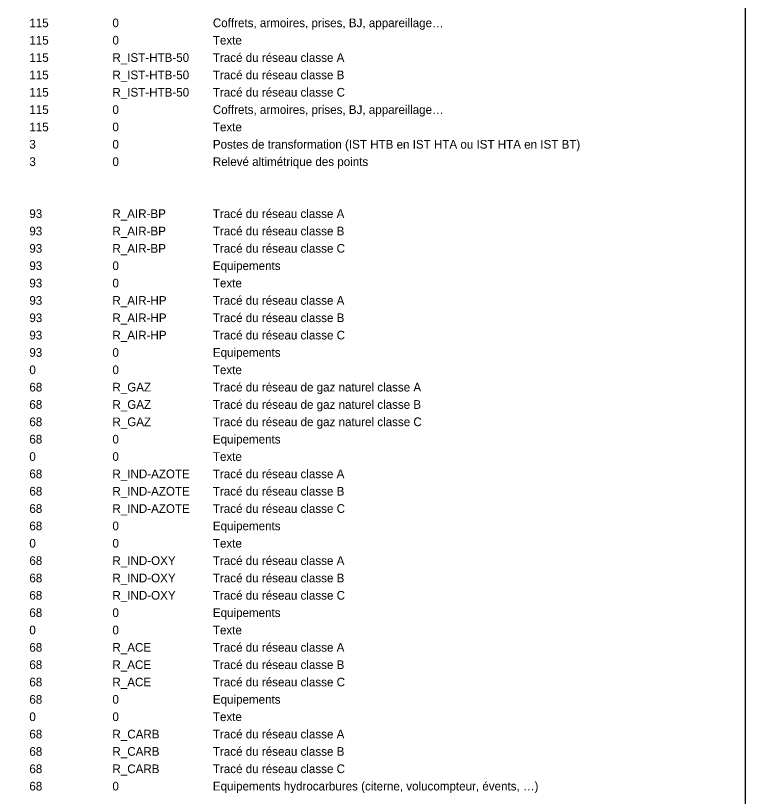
# Model space of a CAD drawing. Extents: x -60 to 214, y -380 to -21.
# Drawn here: x 72.77 to 114.84, y -155.95 to -110.94 of the extents above; entities that cross this region are included whole.
import ezdxf

# ---------------------------------------------------------------- set-up
doc = ezdxf.new("R2010")
doc.units = 0
for name, color, linetype in [('Default', 7, 'Continuous'), ('R_ELEC_IST_ALT_POINT', 7, 'Continuous'), ('R_ELEC_IST_HTA_60HZ_EQUIP', 7, 'Continuous'), ('R_ELEC_IST_HTA_60HZ_TEXTE', 7, 'Continuous'), ('R_ELEC_IST_HTB_50HZ_EQUIP', 7, 'Continuous'), ('R_ELEC_IST_HTB_50HZ_LIAISON_CL_A', 7, 'Continuous'), ('R_ELEC_IST_HTB_50HZ_LIAISON_CL_B', 7, 'Continuous'), ('R_ELEC_IST_HTB_50HZ_LIAISON_CL_C', 7, 'Continuous'), ('R_ELEC_IST_HTB_50HZ_TEXTE', 7, 'Continuous'), ('R_ELEC_IST_POSTE', 7, 'Continuous'), ('R_IND_ACETYLENE_CANALISATION_CL_A', 7, 'Continuous'), ('R_IND_ACETYLENE_CANALISATION_CL_B', 7, 'Continuous'), ('R_IND_ACETYLENE_CANALISATION_CL_C', 7, 'Continuous'), ('R_IND_ACETYLENE_EQUIP', 7, 'Continuous'), ('R_IND_ACETYLENE_TEXTE', 7, 'Continuous'), ('R_IND_AIR_BP_CANALISATION_CL_A', 7, 'Continuous'), ('R_IND_AIR_BP_CANALISATION_CL_B', 7, 'Continuous'), ('R_IND_AIR_BP_CANALISATION_CL_C', 7, 'Continuous'), ('R_IND_AIR_BP_EQUIP', 7, 'Continuous'), ('R_IND_AIR_BP_TEXTE', 7, 'Continuous'), ('R_IND_AIR_HP_CANALISATION_CL_A', 7, 'Continuous'), ('R_IND_AIR_HP_CANALISATION_CL_B', 7, 'Continuous'), ('R_IND_AIR_HP_CANALISATION_CL_C', 7, 'Continuous'), ('R_IND_AIR_HP_EQUIP', 7, 'Continuous'), ('R_IND_AIR_HP_TEXTE', 7, 'Continuous'), ('R_IND_AZOTE_CANALISATION_CL_A', 7, 'Continuous'), ('R_IND_AZOTE_CANALISATION_CL_B', 7, 'Continuous'), ('R_IND_AZOTE_CANALISATION_CL_C', 7, 'Continuous'), ('R_IND_AZOTE_EQUIP', 7, 'Continuous'), ('R_IND_AZOTE_TEXTE', 7, 'Continuous'), ('R_IND_GAZ_NAT_CANALISATION_CL_A', 7, 'Continuous'), ('R_IND_GAZ_NAT_CANALISATION_CL_B', 7, 'Continuous'), ('R_IND_GAZ_NAT_CANALISATION_CL_C', 7, 'Continuous'), ('R_IND_GAZ_NAT_EQUIP', 7, 'Continuous'), ('R_IND_GAZ_NAT_TEXTE', 7, 'Continuous'), ('R_IND_HYDROCARBURE_CANALISATION_CL_A', 7, 'Continuous'), ('R_IND_HYDROCARBURE_CANALISATION_CL_B', 7, 'Continuous'), ('R_IND_HYDROCARBURE_CANALISATION_CL_C', 7, 'Continuous'), ('R_IND_HYDROCARBURE_EQUIP', 7, 'Continuous'), ('R_IND_OXYGENE_CANALISATION_CL_A', 7, 'Continuous'), ('R_IND_OXYGENE_CANALISATION_CL_B', 7, 'Continuous'), ('R_IND_OXYGENE_CANALISATION_CL_C', 7, 'Continuous'), ('R_IND_OXYGENE_EQUIP', 7, 'Continuous'), ('R_IND_OXYGENE_TEXTE', 7, 'Continuous')]:
    doc.layers.add(name, color=color, linetype=linetype)

msp = doc.modelspace()

# ---------------------------------------------------------------- linework, layer by layer
at = {"layer": 'Default'}
msp.add_lwpolyline([(114.838, -25.727), (33.073, -25.727), (33.073, -380.216), (114.838, -380.216)], close=True, dxfattribs=at)

# ---------------------------------------------------------------- texts
at = {"layer": 'R_ELEC_IST_ALT_POINT'}
for s, p in [('3 ', (73.561, -119.61)), ('0 ', (78.351, -119.61)), ('Relevé altimétrique des points ', (84.14, -119.61))]:
    msp.add_text(s, height=0.5, dxfattribs=at).set_placement(p)
at = {"layer": 'R_ELEC_IST_HTA_60HZ_EQUIP'}
for s, p in [('115 ', (73.561, -111.61)), ('0 ', (78.351, -111.61)), ('Coffrets, armoires, prises, BJ, appareillage…', (84.14, -111.61))]:
    msp.add_text(s, height=0.5, dxfattribs=at).set_placement(p)
at = {"layer": 'R_ELEC_IST_HTA_60HZ_TEXTE'}
for s, p in [('115', (73.561, -112.61)), ('0 ', (78.351, -112.61)), ('Texte ', (84.14, -112.61))]:
    msp.add_text(s, height=0.5, dxfattribs=at).set_placement(p)
at = {"layer": 'R_ELEC_IST_HTB_50HZ_EQUIP'}
for s, p in [('115 ', (73.561, -116.61)), ('0 ', (78.351, -116.61)), ('Coffrets, armoires, prises, BJ, appareillage…', (84.14, -116.61))]:
    msp.add_text(s, height=0.5, dxfattribs=at).set_placement(p)
at = {"layer": 'R_ELEC_IST_HTB_50HZ_LIAISON_CL_A'}
for s, p in [('115 ', (73.561, -113.61)), ('R_IST-HTB-50 ', (78.351, -113.61)), ('Tracé du réseau classe A ', (84.14, -113.61))]:
    msp.add_text(s, height=0.5, dxfattribs=at).set_placement(p)
at = {"layer": 'R_ELEC_IST_HTB_50HZ_LIAISON_CL_B'}
for s, p in [('115 ', (73.561, -114.61)), ('R_IST-HTB-50 ', (78.351, -114.61)), ('Tracé du réseau classe B ', (84.14, -114.61))]:
    msp.add_text(s, height=0.5, dxfattribs=at).set_placement(p)
at = {"layer": 'R_ELEC_IST_HTB_50HZ_LIAISON_CL_C'}
for s, p in [('115 ', (73.561, -115.61)), ('R_IST-HTB-50 ', (78.351, -115.61)), ('Tracé du réseau classe C ', (84.14, -115.61))]:
    msp.add_text(s, height=0.5, dxfattribs=at).set_placement(p)
at = {"layer": 'R_ELEC_IST_HTB_50HZ_TEXTE'}
for s, p in [('115 ', (73.561, -117.61)), ('0 ', (78.351, -117.61)), ('Texte ', (84.14, -117.61))]:
    msp.add_text(s, height=0.5, dxfattribs=at).set_placement(p)
at = {"layer": 'R_ELEC_IST_POSTE'}
for s, p in [('3 ', (73.561, -118.61)), ('0 ', (78.351, -118.61)), ('Postes de transformation (IST HTB en IST HTA ou IST HTA en IST BT) ', (84.14, -118.61))]:
    msp.add_text(s, height=0.5, dxfattribs=at).set_placement(p)
at = {"layer": 'R_IND_ACETYLENE_CANALISATION_CL_A'}
for s, p in [('68 ', (73.561, -147.61)), ('R_ACE ', (78.351, -147.61)), ('Tracé du réseau classe A ', (84.14, -147.61))]:
    msp.add_text(s, height=0.5, dxfattribs=at).set_placement(p)
at = {"layer": 'R_IND_ACETYLENE_CANALISATION_CL_B'}
for s, p in [('Tracé du réseau classe B ', (84.14, -148.61)), ('68 ', (73.561, -148.61)), ('R_ACE ', (78.351, -148.61))]:
    msp.add_text(s, height=0.5, dxfattribs=at).set_placement(p)
at = {"layer": 'R_IND_ACETYLENE_CANALISATION_CL_C'}
for s, p in [('68 ', (73.561, -149.61)), ('R_ACE ', (78.351, -149.61)), ('Tracé du réseau classe C ', (84.14, -149.61))]:
    msp.add_text(s, height=0.5, dxfattribs=at).set_placement(p)
at = {"layer": 'R_IND_ACETYLENE_EQUIP'}
for s, p in [('68 ', (73.561, -150.61)), ('0 ', (78.351, -150.61)), ('Equipements ', (84.14, -150.61))]:
    msp.add_text(s, height=0.5, dxfattribs=at).set_placement(p)
at = {"layer": 'R_IND_ACETYLENE_TEXTE'}
for s, p in [('0', (73.561, -151.61)), ('0 ', (78.351, -151.61)), ('Texte ', (84.14, -151.61))]:
    msp.add_text(s, height=0.5, dxfattribs=at).set_placement(p)
at = {"layer": 'R_IND_AIR_BP_CANALISATION_CL_A'}
for s, p in [('93 ', (73.559, -122.61)), ('R_AIR-BP ', (78.348, -122.61)), ('Tracé du réseau classe A ', (84.138, -122.61))]:
    msp.add_text(s, height=0.5, dxfattribs=at).set_placement(p)
at = {"layer": 'R_IND_AIR_BP_CANALISATION_CL_B'}
for s, p in [('93 ', (73.561, -123.61)), ('R_AIR-BP ', (78.351, -123.61)), ('Tracé du réseau classe B ', (84.14, -123.61))]:
    msp.add_text(s, height=0.5, dxfattribs=at).set_placement(p)
at = {"layer": 'R_IND_AIR_BP_CANALISATION_CL_C'}
for s, p in [('93 ', (73.561, -124.61)), ('R_AIR-BP ', (78.351, -124.61)), ('Tracé du réseau classe C ', (84.14, -124.61))]:
    msp.add_text(s, height=0.5, dxfattribs=at).set_placement(p)
at = {"layer": 'R_IND_AIR_BP_EQUIP'}
for s, p in [('93 ', (73.561, -125.61)), ('0 ', (78.351, -125.61)), ('Equipements  ', (84.14, -125.61))]:
    msp.add_text(s, height=0.5, dxfattribs=at).set_placement(p)
at = {"layer": 'R_IND_AIR_BP_TEXTE'}
for s, p in [('93 ', (73.561, -126.61)), ('0 ', (78.351, -126.61)), ('Texte ', (84.14, -126.61))]:
    msp.add_text(s, height=0.5, dxfattribs=at).set_placement(p)
at = {"layer": 'R_IND_AIR_HP_CANALISATION_CL_A'}
for s, p in [('93 ', (73.561, -127.61)), ('R_AIR-HP ', (78.351, -127.61)), ('Tracé du réseau classe A ', (84.14, -127.61))]:
    msp.add_text(s, height=0.5, dxfattribs=at).set_placement(p)
at = {"layer": 'R_IND_AIR_HP_CANALISATION_CL_B'}
for s, p in [('93 ', (73.561, -128.61)), ('R_AIR-HP ', (78.351, -128.61)), ('Tracé du réseau classe B ', (84.14, -128.61))]:
    msp.add_text(s, height=0.5, dxfattribs=at).set_placement(p)
at = {"layer": 'R_IND_AIR_HP_CANALISATION_CL_C'}
for s, p in [('93 ', (73.561, -129.61)), ('R_AIR-HP ', (78.351, -129.61)), ('Tracé du réseau classe C ', (84.14, -129.61))]:
    msp.add_text(s, height=0.5, dxfattribs=at).set_placement(p)
at = {"layer": 'R_IND_AIR_HP_EQUIP'}
for s, p in [('93 ', (73.561, -130.61)), ('0 ', (78.351, -130.61)), ('Equipements ', (84.14, -130.61))]:
    msp.add_text(s, height=0.5, dxfattribs=at).set_placement(p)
at = {"layer": 'R_IND_AIR_HP_TEXTE'}
for s, p in [('0', (73.561, -131.61)), ('0 ', (78.351, -131.61)), ('Texte ', (84.14, -131.61))]:
    msp.add_text(s, height=0.5, dxfattribs=at).set_placement(p)
at = {"layer": 'R_IND_AZOTE_CANALISATION_CL_A'}
for s, p in [('68 ', (73.561, -137.61)), ('R_IND-AZOTE ', (78.351, -137.61)), ('Tracé du réseau classe A ', (84.14, -137.61))]:
    msp.add_text(s, height=0.5, dxfattribs=at).set_placement(p)
at = {"layer": 'R_IND_AZOTE_CANALISATION_CL_B'}
for s, p in [('68 ', (73.561, -138.61)), ('R_IND-AZOTE ', (78.351, -138.61)), ('Tracé du réseau classe B ', (84.14, -138.61))]:
    msp.add_text(s, height=0.5, dxfattribs=at).set_placement(p)
at = {"layer": 'R_IND_AZOTE_CANALISATION_CL_C'}
for s, p in [('Tracé du réseau classe C ', (84.14, -139.61)), ('68 ', (73.561, -139.61)), ('R_IND-AZOTE ', (78.351, -139.61))]:
    msp.add_text(s, height=0.5, dxfattribs=at).set_placement(p)
at = {"layer": 'R_IND_AZOTE_EQUIP'}
for s, p in [('68 ', (73.561, -140.61)), ('0 ', (78.351, -140.61)), ('Equipements ', (84.14, -140.61))]:
    msp.add_text(s, height=0.5, dxfattribs=at).set_placement(p)
at = {"layer": 'R_IND_AZOTE_TEXTE'}
for s, p in [('0', (73.561, -141.61)), ('0 ', (78.351, -141.61)), ('Texte ', (84.14, -141.61))]:
    msp.add_text(s, height=0.5, dxfattribs=at).set_placement(p)
at = {"layer": 'R_IND_GAZ_NAT_CANALISATION_CL_A'}
for s, p in [('68 ', (73.561, -132.61)), ('R_GAZ ', (78.351, -132.61)), ('Tracé du réseau de gaz naturel classe A ', (84.14, -132.61))]:
    msp.add_text(s, height=0.5, dxfattribs=at).set_placement(p)
at = {"layer": 'R_IND_GAZ_NAT_CANALISATION_CL_B'}
for s, p in [('68 ', (73.561, -133.61)), ('R_GAZ ', (78.351, -133.61)), ('Tracé du réseau de gaz naturel classe B ', (84.14, -133.61))]:
    msp.add_text(s, height=0.5, dxfattribs=at).set_placement(p)
at = {"layer": 'R_IND_GAZ_NAT_CANALISATION_CL_C'}
for s, p in [('68 ', (73.561, -134.61)), ('R_GAZ ', (78.351, -134.61)), ('Tracé du réseau de gaz naturel classe C ', (84.14, -134.61))]:
    msp.add_text(s, height=0.5, dxfattribs=at).set_placement(p)
at = {"layer": 'R_IND_GAZ_NAT_EQUIP'}
for s, p in [('68 ', (73.561, -135.61)), ('0 ', (78.351, -135.61)), ('Equipements ', (84.14, -135.61))]:
    msp.add_text(s, height=0.5, dxfattribs=at).set_placement(p)
at = {"layer": 'R_IND_GAZ_NAT_TEXTE'}
for s, p in [('0', (73.561, -136.61)), ('0 ', (78.351, -136.61)), ('Texte ', (84.14, -136.61))]:
    msp.add_text(s, height=0.5, dxfattribs=at).set_placement(p)
at = {"layer": 'R_IND_HYDROCARBURE_CANALISATION_CL_A'}
for s, p in [('68 ', (73.561, -152.61)), ('R_CARB ', (78.351, -152.61)), ('Tracé du réseau classe A ', (84.14, -152.61))]:
    msp.add_text(s, height=0.5, dxfattribs=at).set_placement(p)
at = {"layer": 'R_IND_HYDROCARBURE_CANALISATION_CL_B'}
for s, p in [('68 ', (73.561, -153.61)), ('R_CARB ', (78.351, -153.61)), ('Tracé du réseau classe B ', (84.14, -153.61))]:
    msp.add_text(s, height=0.5, dxfattribs=at).set_placement(p)
at = {"layer": 'R_IND_HYDROCARBURE_CANALISATION_CL_C'}
for s, p in [('68 ', (73.561, -154.61)), ('R_CARB ', (78.351, -154.61)), ('Tracé du réseau classe C ', (84.14, -154.61))]:
    msp.add_text(s, height=0.5, dxfattribs=at).set_placement(p)
at = {"layer": 'R_IND_HYDROCARBURE_EQUIP'}
for s, p in [('68 ', (73.561, -155.61)), ('0 ', (78.351, -155.61)), ('Equipements hydrocarbures (citerne, volucompteur, évents, …)  ', (84.14, -155.61))]:
    msp.add_text(s, height=0.5, dxfattribs=at).set_placement(p)
at = {"layer": 'R_IND_OXYGENE_CANALISATION_CL_A'}
for s, p in [('68 ', (73.561, -142.61)), ('R_IND-OXY ', (78.351, -142.61)), ('Tracé du réseau classe A ', (84.14, -142.61))]:
    msp.add_text(s, height=0.5, dxfattribs=at).set_placement(p)
at = {"layer": 'R_IND_OXYGENE_CANALISATION_CL_B'}
for s, p in [('68 ', (73.561, -143.61)), ('R_IND-OXY ', (78.351, -143.61)), ('Tracé du réseau classe B ', (84.14, -143.61))]:
    msp.add_text(s, height=0.5, dxfattribs=at).set_placement(p)
at = {"layer": 'R_IND_OXYGENE_CANALISATION_CL_C'}
for s, p in [('68 ', (73.561, -144.61)), ('R_IND-OXY ', (78.351, -144.61)), ('Tracé du réseau classe C ', (84.14, -144.61))]:
    msp.add_text(s, height=0.5, dxfattribs=at).set_placement(p)
at = {"layer": 'R_IND_OXYGENE_EQUIP'}
for s, p in [('68 ', (73.561, -145.61)), ('0 ', (78.351, -145.61)), ('Equipements ', (84.14, -145.61))]:
    msp.add_text(s, height=0.5, dxfattribs=at).set_placement(p)
at = {"layer": 'R_IND_OXYGENE_TEXTE'}
for s, p in [('0', (73.561, -146.61)), ('0 ', (78.351, -146.61)), ('Texte ', (84.14, -146.61))]:
    msp.add_text(s, height=0.5, dxfattribs=at).set_placement(p)

doc.saveas('drawing.dxf')
